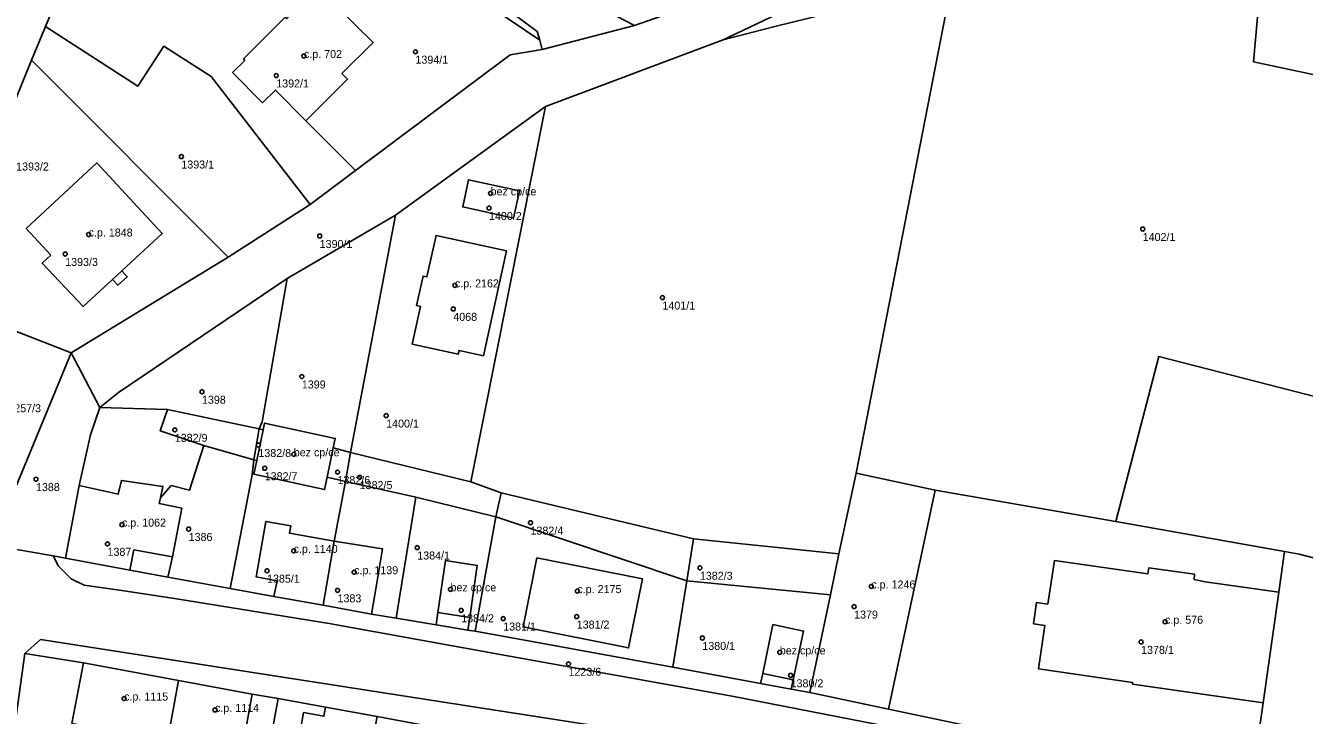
# Model space of a CAD drawing. Extents: x -878211 to -870363, y -1058464 to -1052522.
# Drawn here: x -875300.1 to -875140.3, y -1056255.7 to -1056169.5 of the extents above; entities that cross this region are included whole.
import ezdxf

# ---------------------------------------------------------------- set-up
doc = ezdxf.new("R2010")
doc.units = 0
for name, color, linetype in [('Vrstva 50', 7, 'Continuous'), ('Vrstva 51', 7, 'Continuous'), ('Vrstva 52', 7, 'Continuous')]:
    doc.layers.add(name, color=color, linetype=linetype)

msp = doc.modelspace()

# ---------------------------------------------------------------- linework, layer by layer
at = {"layer": 'Vrstva 50'}
for centre in [(-875265.33, -1056173.32994), (-875251.39, -1056172.79994), (-875268.79, -1056175.76994), (-875280.65, -1056185.89994), (-875242, -1056190.49994), (-875242.2, -1056192.33994), (-875292.24, -1056195.63994), (-875263.36, -1056195.82994), (-875160.49, -1056194.95994), (-875295.17, -1056198.07994), (-875246.46, -1056201.99994), (-875220.52, -1056203.52994), (-875246.66, -1056204.93994), (-875265.59, -1056213.38994), (-875278.07, -1056215.29994), (-875255.05, -1056218.27994), (-875281.47, -1056220.05994), (-875271.02, -1056221.95994), (-875266.6, -1056223.10994), (-875298.82, -1056226.21994), (-875270.23, -1056224.85994), (-875261.13, -1056225.33994), (-875258.36, -1056225.96994), (-875288.07, -1056231.89994), (-875279.74, -1056232.44994), (-875237.01, -1056231.65994), (-875289.88, -1056234.30994), (-875266.62, -1056235.17994), (-875251.17, -1056234.76994), (-875215.84, -1056237.29994), (-875269.94, -1056237.66994), (-875259.05, -1056237.84994), (-875261.13, -1056240.11994), (-875247.01, -1056239.98994), (-875231.15, -1056240.20994), (-875194.41, -1056239.62994), (-875196.56, -1056242.14994), (-875245.67, -1056242.61994), (-875240.42, -1056243.64994), (-875231.23, -1056243.39994), (-875157.7, -1056244.03994), (-875215.53, -1056246.06994), (-875160.69, -1056246.55994), (-875205.85, -1056247.86994), (-875232.26, -1056249.29994), (-875204.5, -1056250.73994), (-875287.8, -1056253.63994), (-875276.44, -1056255.05994)]:
    msp.add_circle(centre, 0.25, dxfattribs=at)
at = {"layer": 'Vrstva 51'}
for points in [[(-875235.55, -1056172.5), (-875224.03, -1056169.51), (-875284.65, -1056138), (-875288.65, -1056147.77), (-875283.69, -1056150.47), (-875284.07, -1056149.18), (-875283.25, -1056147.67), (-875281.92, -1056147.31), (-875281.52, -1056147.53), (-875279.88, -1056144.53), (-875278.47, -1056145.25), (-875277.82, -1056144.08), (-875277.19, -1056143.92), (-875275.46, -1056144.88), (-875276.26, -1056146.35), (-875268.56, -1056150.32), (-875271.94, -1056156.88), (-875264.61, -1056159.37), (-875257.82, -1056156.61), (-875249.38, -1056162.19), (-875246.96, -1056162.9), (-875242.78, -1056165.31), (-875236.18, -1056170.26), (-875235.86, -1056171.36)], [(-875256.68, -1056171.63), (-875263.58, -1056164.8), (-875265.96, -1056161.17), (-875270.79, -1056162.56), (-875273.59, -1056164.03), (-875274.65, -1056163.65), (-875291.76, -1056155.38), (-875297.64, -1056169.65), (-875295.27, -1056171.18), (-875286.1, -1056177.11), (-875282.83, -1056172.11), (-875276.92, -1056175.9), (-875264.53, -1056191.88), (-875258.88, -1056187.65), (-875265.07, -1056181.43), (-875259.87, -1056176.22), (-875260.58, -1056175.53)], [(-875290.85, -1056217.25), (-875288.51, -1056215.39), (-875267.42, -1056201.14), (-875253.87, -1056193.24), (-875235.15, -1056179.64), (-875212.93, -1056171.29), (-875198.54, -1056164.44), (-875186.84, -1056159.04), (-875187.71, -1056154.75), (-875191.28, -1056156.59), (-875191.96, -1056156.16), (-875207.81, -1056163.82), (-875224.03, -1056169.51), (-875235.55, -1056172.5), (-875239.56, -1056173.18), (-875258.88, -1056187.65), (-875264.53, -1056191.88), (-875274.81, -1056198.46), (-875294.42, -1056210.42)], [(-875145.85, -1056165.17), (-875172.11, -1056160.17), (-875181.94, -1056158.3), (-875183.39, -1056159.14), (-875185.11, -1056167.99), (-875196.31, -1056225.45), (-875186.44, -1056227.59), (-875163.85, -1056231.52), (-875158.49, -1056210.9), (-875129.45, -1056218.36), (-875120.61, -1056179.58), (-875146.64, -1056174.06)], [(-875252.26, -1056161.46), (-875264.61, -1056159.37), (-875264.75, -1056160.24), (-875265.96, -1056161.17), (-875263.58, -1056164.8), (-875256.68, -1056171.63), (-875260.58, -1056175.53), (-875259.87, -1056176.22), (-875265.07, -1056181.43), (-875258.88, -1056187.65), (-875239.56, -1056173.18), (-875235.55, -1056172.5), (-875235.86, -1056171.36), (-875249.38, -1056162.19)], [(-875185.11, -1056167.99), (-875183.39, -1056159.14), (-875184.98, -1056160.07), (-875188.92, -1056162.13), (-875193.34, -1056164.06), (-875197.47, -1056165.78), (-875198.54, -1056164.44), (-875212.93, -1056171.29), (-875206.49, -1056169.65), (-875197.79, -1056167.52), (-875191.78, -1056167.08)], [(-875249.38, -1056162.19), (-875235.86, -1056171.36), (-875236.18, -1056170.26), (-875242.78, -1056165.31), (-875246.96, -1056162.9)], [(-875244.48, -1056226.55), (-875240.66, -1056227.91), (-875216.63, -1056233.68), (-875198.45, -1056235.57), (-875196.31, -1056225.45), (-875185.11, -1056167.99), (-875191.78, -1056167.08), (-875197.79, -1056167.52), (-875206.49, -1056169.65), (-875212.93, -1056171.29), (-875235.15, -1056179.64)], [(-875274.81, -1056198.46), (-875264.53, -1056191.88), (-875276.92, -1056175.9), (-875282.83, -1056172.11), (-875286.1, -1056177.11), (-875295.27, -1056171.18), (-875297.64, -1056169.65), (-875299.37, -1056173.85)], [(-875311.54, -1056203.77), (-875294.42, -1056210.42), (-875274.81, -1056198.46), (-875299.37, -1056173.85)], [(-875259.49, -1056222.87), (-875244.48, -1056226.55), (-875235.15, -1056179.64), (-875253.87, -1056193.24)], [(-875296.96, -1056198.2), (-875298.06, -1056199.23), (-875292.94, -1056204.64), (-875289.26, -1056201.25), (-875288.58, -1056201.99), (-875287.41, -1056200.91), (-875288.08, -1056200.17), (-875283.04, -1056195.53), (-875291.22, -1056186.69), (-875300.04, -1056194.9)], [(-875296.96, -1056198.2), (-875300.04, -1056194.9), (-875291.22, -1056186.69), (-875283.04, -1056195.53), (-875288.08, -1056200.17), (-875287.41, -1056200.91), (-875288.58, -1056201.99), (-875289.26, -1056201.25), (-875292.94, -1056204.64), (-875298.06, -1056199.23)], [(-875239.14, -1056193.61), (-875245.48, -1056192.2), (-875244.74, -1056188.8), (-875238.38, -1056190.2)], [(-875239.14, -1056193.61), (-875238.38, -1056190.2), (-875244.74, -1056188.8), (-875245.48, -1056192.2)], [(-875306.46, -1056234.09), (-875304.4, -1056234.45), (-875294.42, -1056210.42), (-875311.54, -1056203.77), (-875324.26, -1056198.11), (-875340.01, -1056191.03), (-875340.69, -1056192.98), (-875334.17, -1056195.52), (-875318.79, -1056203.03), (-875301.54, -1056208.96), (-875302, -1056211.32), (-875303.12, -1056217.01), (-875304.54, -1056224.28)], [(-875270.25, -1056219.21), (-875261.41, -1056221.12), (-875261.66, -1056222.31), (-875259.49, -1056222.87), (-875253.87, -1056193.24), (-875267.42, -1056201.14), (-875270.53, -1056219.07), (-875270.91, -1056219.91), (-875270.42, -1056220.04)], [(-875240.02, -1056197.67), (-875242.9, -1056210.79), (-875245.93, -1056210.13), (-875246.03, -1056210.61), (-875251.78, -1056209.35), (-875250.76, -1056204.62), (-875251.24, -1056204.51), (-875250.43, -1056200.84), (-875249.96, -1056200.93), (-875248.81, -1056195.75)], [(-875240.02, -1056197.67), (-875248.81, -1056195.75), (-875249.96, -1056200.93), (-875250.43, -1056200.84), (-875251.24, -1056204.51), (-875250.76, -1056204.62), (-875251.78, -1056209.35), (-875246.03, -1056210.61), (-875245.93, -1056210.13), (-875242.9, -1056210.79)], [(-875288.51, -1056215.39), (-875290.85, -1056217.25), (-875282.37, -1056217.51), (-875270.91, -1056219.91), (-875270.53, -1056219.07), (-875267.42, -1056201.14)], [(-875295.13, -1056236.08), (-875293.44, -1056227.02), (-875292.01, -1056220.68), (-875290.85, -1056217.25), (-875294.42, -1056210.42), (-875304.4, -1056234.45), (-875296.66, -1056235.81)], [(-875129.45, -1056218.36), (-875158.49, -1056210.9), (-875163.85, -1056231.52), (-875142.76, -1056235.27), (-875140.94, -1056235.59), (-875116.46, -1056241.92), (-875109.03, -1056242.99), (-875109.2, -1056244.17), (-875104.05, -1056244.91), (-875104.03, -1056244.73), (-875096.96, -1056245.76), (-875089.5, -1056246.85), (-875088.46, -1056238.93), (-875089.68, -1056238.77), (-875088.35, -1056228.86)], [(-875287.07, -1056237.59), (-875282.33, -1056238.46), (-875281.75, -1056235.93), (-875280.6, -1056229.86), (-875283.42, -1056229.24), (-875283.27, -1056228.56), (-875281.91, -1056227.02), (-875279.63, -1056227.58), (-875277.82, -1056221.99), (-875283.28, -1056220.17), (-875282.37, -1056217.51), (-875290.85, -1056217.25), (-875292.01, -1056220.68), (-875293.44, -1056227.02), (-875295.13, -1056236.08)], [(-875271.59, -1056223.79), (-875270.91, -1056219.91), (-875282.37, -1056217.51), (-875283.28, -1056220.17), (-875277.82, -1056221.99)], [(-875271.23, -1056223.88), (-875271.59, -1056225.61), (-875262.75, -1056227.51), (-875262.43, -1056225.96), (-875261.66, -1056222.31), (-875261.41, -1056221.12), (-875270.25, -1056219.21), (-875270.42, -1056220.04)], [(-875271.23, -1056223.88), (-875270.42, -1056220.04), (-875270.91, -1056219.91), (-875271.59, -1056223.79)], [(-875274.55, -1056239.87), (-875271.81, -1056225.66), (-875271.59, -1056223.79), (-875277.82, -1056221.99), (-875279.63, -1056227.58), (-875281.91, -1056227.02), (-875283.27, -1056228.56), (-875283.42, -1056229.24), (-875280.6, -1056229.86), (-875281.75, -1056235.93), (-875282.33, -1056238.46)], [(-875262.43, -1056225.96), (-875260.15, -1056226.5), (-875259.49, -1056222.87), (-875261.66, -1056222.31)], [(-875271.59, -1056223.79), (-875271.81, -1056225.66), (-875274.55, -1056239.87), (-875269.1, -1056240.9), (-875262.93, -1056241.98), (-875261.53, -1056233.95), (-875260.15, -1056226.5), (-875262.43, -1056225.96), (-875262.75, -1056227.51), (-875271.59, -1056225.61), (-875271.23, -1056223.88)], [(-875260.15, -1056226.5), (-875251.35, -1056228.47), (-875241.35, -1056230.93), (-875240.66, -1056227.91), (-875244.48, -1056226.55), (-875259.49, -1056222.87)], [(-875192.25, -1056254.98), (-875186.44, -1056227.59), (-875196.31, -1056225.45), (-875198.45, -1056235.57), (-875199.52, -1056240.66), (-875202.1, -1056252.89)], [(-875262.93, -1056241.98), (-875256.9, -1056243.07), (-875253.79, -1056243.58), (-875253.42, -1056241.27), (-875252.47, -1056235.4), (-875251.35, -1056228.47), (-875260.15, -1056226.5), (-875261.53, -1056233.95)], [(-875192.25, -1056254.98), (-875171.65, -1056259.31), (-875146.64, -1056262.62), (-875145.45, -1056254.19), (-875143.49, -1056240.36), (-875142.76, -1056235.27), (-875163.85, -1056231.52), (-875186.44, -1056227.59)], [(-875244.84, -1056245.07), (-875243.91, -1056245.22), (-875241.35, -1056230.93), (-875251.35, -1056228.47), (-875252.47, -1056235.4), (-875253.42, -1056241.27), (-875253.79, -1056243.58), (-875248.8, -1056244.41), (-875248.58, -1056242.9), (-875247.65, -1056236.4), (-875243.66, -1056237), (-875244.61, -1056243.49)], [(-875217.47, -1056238.94), (-875216.63, -1056233.68), (-875240.66, -1056227.91), (-875241.35, -1056230.93)], [(-875217.47, -1056238.94), (-875241.35, -1056230.93), (-875243.91, -1056245.22), (-875219.21, -1056249.73)], [(-875217.47, -1056238.94), (-875199.52, -1056240.66), (-875198.45, -1056235.57), (-875216.63, -1056233.68)], [(-875146.64, -1056262.62), (-875100.28, -1056268.85), (-875099.3, -1056262.14), (-875092.6, -1056263.05), (-875091.28, -1056254.4), (-875090.54, -1056254.77), (-875089.5, -1056246.85), (-875096.96, -1056245.76), (-875099.09, -1056260.33), (-875130.54, -1056255.84), (-875128.5, -1056241.21), (-875121.77, -1056242.17), (-875121.8, -1056242.36), (-875116.62, -1056243.08), (-875116.46, -1056241.92), (-875140.94, -1056235.59), (-875142.76, -1056235.27), (-875143.49, -1056240.36), (-875145.45, -1056254.19)], [(-875244.84, -1056245.07), (-875244.61, -1056243.49), (-875243.66, -1056237), (-875247.65, -1056236.4), (-875248.58, -1056242.9), (-875248.8, -1056244.41)], [(-875223.02, -1056238.67), (-875236.2, -1056236.07), (-875237.94, -1056244.68), (-875224.74, -1056247.31)], [(-875223.02, -1056238.67), (-875224.74, -1056247.31), (-875237.94, -1056244.68), (-875236.2, -1056236.07)], [(-875204.41, -1056252.46), (-875202.1, -1056252.89), (-875199.52, -1056240.66), (-875217.47, -1056238.94), (-875219.21, -1056249.73), (-875208.25, -1056251.75), (-875207.99, -1056250.51), (-875206.7, -1056244.4), (-875202.88, -1056245.21), (-875204.17, -1056251.31)], [(-875204.41, -1056252.46), (-875204.17, -1056251.31), (-875202.88, -1056245.21), (-875206.7, -1056244.4), (-875207.99, -1056250.51), (-875208.25, -1056251.75)], [(-875296.77, -1056265.83), (-875293.89, -1056266.2), (-875283.04, -1056262.38), (-875282.38, -1056258.92), (-875281.01, -1056251.4), (-875292.88, -1056249.17), (-875300.2, -1056248.02), (-875302.02, -1056260.98), (-875300.08, -1056262.78), (-875300.32, -1056264.94)], [(-875271.98, -1056271.99), (-875271.46, -1056269.45), (-875270.29, -1056263.17), (-875268.54, -1056253.62), (-875271.78, -1056253.11), (-875281.01, -1056251.4), (-875282.38, -1056258.92), (-875283.04, -1056262.38), (-875284.55, -1056269.53)], [(-875262.65, -1056254.71), (-875268.54, -1056253.62), (-875270.29, -1056263.17), (-875271.46, -1056269.45), (-875267.49, -1056270.24), (-875258.69, -1056268.66), (-875258.28, -1056266.65), (-875257.59, -1056263.34), (-875256.18, -1056255.88)]]:
    msp.add_lwpolyline(points, close=True, dxfattribs=at)
for points in [[(-875145.85, -1056165.17), (-875146.64, -1056174.06), (-875120.61, -1056179.58), (-875129.45, -1056218.36), (-875088.35, -1056228.86), (-875087.17, -1056229.16), (-875079.79, -1056231.03), (-875060.67, -1056235.89), (-875040.65, -1056240.85), (-875019.54, -1056246.02), (-875000.03, -1056198.37), (-875001.67, -1056197.91), (-875003.32, -1056180.72), (-875002.28, -1056177.8), (-875001.86, -1056170.38), (-875000.45, -1056147.03)], [(-875399.89, -1056168.76), (-875399.62, -1056170.07), (-875399.26, -1056171.8), (-875397.59, -1056174.66), (-875394.97, -1056176.67), (-875391.88, -1056178.24), (-875390.78, -1056178.58), (-875377.06, -1056181.43), (-875362.64, -1056183.58), (-875353.83, -1056185.59), (-875349.82, -1056187.06), (-875340.01, -1056191.03), (-875324.26, -1056198.11), (-875311.54, -1056203.77), (-875299.37, -1056173.85), (-875297.64, -1056169.65), (-875291.76, -1056155.38)], [(-875294.43, -1056238.67), (-875295.99, -1056237.1), (-875296.66, -1056235.81), (-875304.4, -1056234.45), (-875305.07, -1056235.71), (-875306.31, -1056236.71), (-875307.94, -1056237.08), (-875333.74, -1056232.49), (-875355.38, -1056228.43), (-875384.12, -1056222.95), (-875404.97, -1056218.91), (-875429.25, -1056214.23)], [(-875171.65, -1056259.31), (-875192.25, -1056254.98), (-875202.1, -1056252.89), (-875204.41, -1056252.46), (-875208.25, -1056251.75), (-875219.21, -1056249.73), (-875243.91, -1056245.22), (-875244.84, -1056245.07), (-875248.8, -1056244.41), (-875253.79, -1056243.58), (-875256.9, -1056243.07), (-875262.93, -1056241.98), (-875269.1, -1056240.9), (-875274.55, -1056239.87), (-875282.33, -1056238.46), (-875287.07, -1056237.59), (-875295.13, -1056236.08), (-875296.66, -1056235.81), (-875295.99, -1056237.1), (-875294.43, -1056238.67), (-875292.78, -1056239.47), (-875288.38, -1056240.11), (-875281.49, -1056241.14), (-875262.18, -1056244.25), (-875239.65, -1056248.32), (-875211.79, -1056253.35), (-875178.88, -1056259.75)], [(-875134.42, -1056266.24), (-875168.5, -1056261.62), (-875178.88, -1056259.75), (-875211.79, -1056253.35), (-875239.65, -1056248.32), (-875262.18, -1056244.25), (-875281.49, -1056241.14), (-875288.38, -1056240.11), (-875292.78, -1056239.47), (-875294.43, -1056238.67)], [(-875076.87, -1056280.65), (-875298.24, -1056246.26), (-875300.2, -1056248.02), (-875292.88, -1056249.17), (-875281.01, -1056251.4), (-875271.78, -1056253.11), (-875268.54, -1056253.62), (-875262.65, -1056254.71), (-875256.18, -1056255.88), (-875249.73, -1056257.07), (-875244.49, -1056257.99), (-875242.9, -1056258.33), (-875234.19, -1056259.84), (-875225.15, -1056261.48), (-875220.93, -1056262.2), (-875206.4, -1056264.8), (-875202.57, -1056265.49), (-875194.86, -1056266.4), (-875180.06, -1056268.76), (-875171.07, -1056270.14), (-875165.93, -1056270.84), (-875154.56, -1056272.47), (-875143.8, -1056273.98), (-875134.93, -1056275.24)], [(-875300.2, -1056248.02), (-875298.24, -1056246.26), (-875076.87, -1056280.65)]]:
    msp.add_lwpolyline(points, dxfattribs=at)
at = {"layer": 'Vrstva 52'}
for points in [[(-875272.72, -1056173.87), (-875274.25, -1056175.38), (-875270.52, -1056179.18), (-875268.9, -1056177.58), (-875265.07, -1056181.43), (-875259.87, -1056176.22), (-875260.58, -1056175.53), (-875256.68, -1056171.63), (-875263.58, -1056164.8), (-875267.46, -1056168.65), (-875267.66, -1056168.48), (-875272.88, -1056173.68)], [(-875296.96, -1056198.2), (-875298.06, -1056199.23), (-875292.94, -1056204.64), (-875289.26, -1056201.25), (-875288.08, -1056200.17), (-875283.04, -1056195.53), (-875291.22, -1056186.69), (-875300.04, -1056194.9)], [(-875245.48, -1056192.2), (-875239.14, -1056193.61), (-875238.38, -1056190.2), (-875244.74, -1056188.8)], [(-875242.9, -1056210.79), (-875240.02, -1056197.67), (-875248.81, -1056195.75), (-875249.96, -1056200.93), (-875250.43, -1056200.84), (-875251.24, -1056204.51), (-875250.76, -1056204.62), (-875251.78, -1056209.35), (-875246.03, -1056210.61), (-875245.93, -1056210.13)], [(-875271.59, -1056225.61), (-875262.75, -1056227.51), (-875262.43, -1056225.96), (-875261.66, -1056222.31), (-875261.41, -1056221.12), (-875270.25, -1056219.21), (-875270.42, -1056220.04), (-875271.23, -1056223.88)], [(-875199.52, -1056240.66), (-875202.1, -1056252.89), (-875192.25, -1056254.98), (-875186.44, -1056227.59), (-875196.31, -1056225.45), (-875198.45, -1056235.57)], [(-875295.13, -1056236.08), (-875287.07, -1056237.59), (-875286.57, -1056235.05), (-875281.75, -1056235.93), (-875280.6, -1056229.86), (-875283.42, -1056229.24), (-875283.27, -1056228.56), (-875282.95, -1056227.13), (-875288.14, -1056226.37), (-875288.53, -1056228.11), (-875293.44, -1056227.02)], [(-875261.53, -1056233.95), (-875267.14, -1056232.97), (-875266.97, -1056232.03), (-875270.08, -1056231.49), (-875271.31, -1056238.41), (-875268.69, -1056238.93), (-875269.1, -1056240.9), (-875262.93, -1056241.98)], [(-875262.93, -1056241.98), (-875256.9, -1056243.07), (-875256.48, -1056240.68), (-875255.49, -1056234.92), (-875261.53, -1056233.95)], [(-875248.58, -1056242.9), (-875244.61, -1056243.49), (-875243.66, -1056237), (-875247.65, -1056236.4)], [(-875237.94, -1056244.68), (-875224.74, -1056247.31), (-875223.02, -1056238.67), (-875236.2, -1056236.07)], [(-875174.13, -1056244.28), (-875172.74, -1056244.5), (-875173.5, -1056249.94), (-875161.75, -1056251.63), (-875161.76, -1056251.82), (-875145.45, -1056254.19), (-875143.49, -1056240.36), (-875152.69, -1056239.03), (-875154.04, -1056238.77), (-875154.02, -1056238.09), (-875159.74, -1056237.3), (-875159.84, -1056238.04), (-875171.53, -1056236.39), (-875172.36, -1056241.84), (-875173.77, -1056241.64)], [(-875206.7, -1056244.4), (-875207.99, -1056250.51), (-875204.17, -1056251.31), (-875202.88, -1056245.21)], [(-875294.32, -1056256.77), (-875282.38, -1056258.92), (-875281.01, -1056251.4), (-875292.88, -1056249.17)], [(-875281.01, -1056251.4), (-875282.38, -1056258.92), (-875273.19, -1056260.62), (-875271.78, -1056253.11)], [(-875265.38, -1056255.4), (-875266.47, -1056261.69), (-875257.59, -1056263.34), (-875256.18, -1056255.88), (-875262.65, -1056254.71), (-875262.84, -1056255.83)]]:
    msp.add_lwpolyline(points, close=True, dxfattribs=at)

# ---------------------------------------------------------------- texts
at = {"layer": 'Vrstva 50'}
for s, p in [('c.p. 702', (-875265.33, -1056173.58)), ('1394/1', (-875251.39, -1056174.289)), ('1392/1', (-875268.79, -1056177.259)), ('1393/2', (-875301.3, -1056187.639)), ('1393/1', (-875280.65, -1056187.389)), ('bez cp/ce', (-875242, -1056190.75)), ('1400/2', (-875242.2, -1056193.829)), ('c.p. 1848', (-875292.24, -1056195.889)), ('1402/1', (-875160.49, -1056196.449)), ('1390/1', (-875263.36, -1056197.319)), ('1393/3', (-875295.17, -1056199.569)), ('c.p. 2162', (-875246.46, -1056202.25)), ('1401/1', (-875220.52, -1056205.019)), ('4068', (-875246.66, -1056206.429)), ('1399', (-875265.59, -1056214.879)), ('1398', (-875278.07, -1056216.789)), ('1257/3', (-875302.28, -1056217.849)), ('1400/1', (-875255.05, -1056219.769)), ('1382/9', (-875281.47, -1056221.549)), ('1382/8', (-875271.02, -1056223.449)), ('bez cp/ce', (-875266.6, -1056223.36)), ('1382/7', (-875270.23, -1056226.349)), ('1382/6', (-875261.13, -1056226.829)), ('1388', (-875298.82, -1056227.709)), ('1382/5', (-875258.36, -1056227.459)), ('c.p. 1062', (-875288.07, -1056232.149)), ('1382/4', (-875237.01, -1056233.149)), ('1386', (-875279.74, -1056233.939)), ('1387', (-875289.88, -1056235.799)), ('c.p. 1140', (-875266.62, -1056235.429)), ('1384/1', (-875251.17, -1056236.259)), ('c.p. 1139', (-875259.05, -1056238.1)), ('1385/1', (-875269.94, -1056239.159)), ('1382/3', (-875215.84, -1056238.789)), ('bez cp/ce', (-875247.01, -1056240.24)), ('c.p. 2175', (-875231.15, -1056240.46)), ('c.p. 1246', (-875194.41, -1056239.879)), ('1383', (-875261.13, -1056241.609)), ('1384/2', (-875245.67, -1056244.109)), ('1379', (-875196.56, -1056243.639)), ('c.p. 576', (-875157.7, -1056244.29)), ('1381/1', (-875240.42, -1056245.139)), ('1381/2', (-875231.23, -1056244.889)), ('1380/1', (-875215.53, -1056247.559)), ('bez cp/ce', (-875205.85, -1056248.12)), ('1378/1', (-875160.69, -1056248.049)), ('1223/6', (-875232.26, -1056250.789)), ('1380/2', (-875204.5, -1056252.229)), ('c.p. 1115', (-875287.8, -1056253.889)), ('c.p. 1114', (-875276.44, -1056255.31))]:
    msp.add_text(s, height=0.999996, dxfattribs=at).set_placement(p)

doc.saveas('drawing.dxf')
